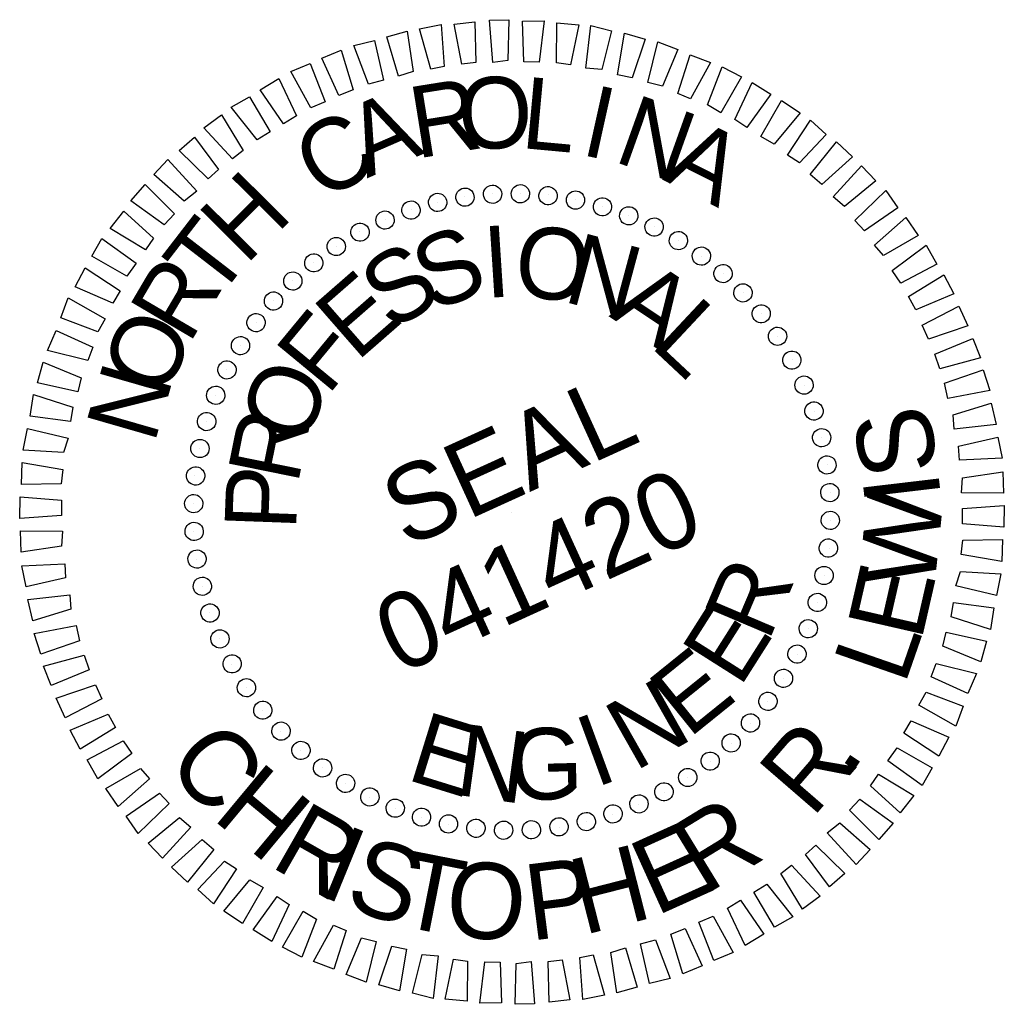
# Model space of a CAD drawing. Extents: x 2247910 to 2249896, y 662531 to 664300.
# Drawn here: x 2249756.6 to 2249834.1, y 664222.2 to 664299.8 of the extents above; entities that cross this region are included whole.
import ezdxf

# ---------------------------------------------------------------- set-up
doc = ezdxf.new("R2010")
doc.units = 0
doc.layers.add('Sheet PE Seal Cell', color=7, linetype='Continuous')

msp = doc.modelspace()

# ---------------------------------------------------------------- linework, layer by layer
at = {"layer": 'Sheet PE Seal Cell'}
for p, q in [((2249793.82, 664286.071), (2249793.82, 664286.071)), ((2249796.013, 664286.082), (2249796.013, 664286.082)), ((2249798.202, 664285.98), (2249798.202, 664285.98)), ((2249789.521, 664285.376), (2249789.521, 664285.376)), ((2249791.619, 664285.838), (2249791.619, 664285.838)), ((2249800.359, 664285.589), (2249800.359, 664285.589)), ((2249787.42, 664284.803), (2249787.42, 664284.803)), ((2249802.511, 664285.086), (2249802.511, 664285.086)), ((2249804.543, 664284.364), (2249804.543, 664284.364)), ((2249785.356, 664284.027), (2249785.356, 664284.027)), ((2249783.374, 664283.07), (2249783.374, 664283.07)), ((2249806.592, 664283.485), (2249806.592, 664283.485)), ((2249808.456, 664282.411), (2249808.456, 664282.411)), ((2249781.542, 664281.905), (2249781.542, 664281.905)), ((2249779.706, 664280.629), (2249779.706, 664280.629)), ((2249810.29, 664281.159), (2249810.29, 664281.159)), ((2249812.008, 664279.799), (2249812.008, 664279.799)), ((2249778.044, 664279.212), (2249778.044, 664279.212)), ((2249813.566, 664278.31), (2249813.566, 664278.31)), ((2249776.556, 664277.655), (2249776.556, 664277.655)), ((2249814.982, 664276.648), (2249814.982, 664276.648)), ((2249775.196, 664275.936), (2249775.196, 664275.936)), ((2249816.259, 664274.812), (2249816.259, 664274.812)), ((2249773.944, 664274.102), (2249773.944, 664274.102)), ((2249817.423, 664272.98), (2249817.423, 664272.98)), ((2249772.87, 664272.239), (2249772.87, 664272.239)), ((2249818.381, 664270.999), (2249818.381, 664270.999)), ((2249771.99, 664270.19), (2249771.99, 664270.19)), ((2249819.157, 664268.935), (2249819.157, 664268.935)), ((2249771.268, 664268.157), (2249771.268, 664268.157)), ((2249819.73, 664266.833), (2249819.73, 664266.833)), ((2249770.765, 664266.005), (2249770.765, 664266.005)), ((2249820.191, 664264.736), (2249820.191, 664264.736)), ((2249770.374, 664263.849), (2249770.374, 664263.849)), ((2249820.425, 664262.535), (2249820.425, 664262.535)), ((2249770.273, 664261.66), (2249770.273, 664261.66)), ((2249795.354, 664261), (2249795.354, 664261)), ((2249820.435, 664260.341), (2249820.435, 664260.341)), ((2249770.283, 664259.466), (2249770.283, 664259.466)), ((2249820.334, 664258.152), (2249820.334, 664258.152)), ((2249770.517, 664257.265), (2249770.517, 664257.265)), ((2249819.943, 664255.996), (2249819.943, 664255.996)), ((2249770.978, 664255.168), (2249770.978, 664255.168)), ((2249819.44, 664253.844), (2249819.44, 664253.844)), ((2249771.551, 664253.066), (2249771.551, 664253.066)), ((2249818.718, 664251.811), (2249818.718, 664251.811)), ((2249772.327, 664251.002), (2249772.327, 664251.002)), ((2249817.838, 664249.762), (2249817.838, 664249.762)), ((2249773.285, 664249.021), (2249773.285, 664249.021)), ((2249774.449, 664247.189), (2249774.449, 664247.189)), ((2249816.764, 664247.899), (2249816.764, 664247.899)), ((2249815.512, 664246.065), (2249815.512, 664246.065)), ((2249775.726, 664245.353), (2249775.726, 664245.353)), ((2249814.152, 664244.346), (2249814.152, 664244.346)), ((2249777.142, 664243.691), (2249777.142, 664243.691)), ((2249812.664, 664242.789), (2249812.664, 664242.789)), ((2249778.7, 664242.202), (2249778.7, 664242.202)), ((2249811.002, 664241.372), (2249811.002, 664241.372)), ((2249780.418, 664240.842), (2249780.418, 664240.842)), ((2249782.252, 664239.59), (2249782.252, 664239.59)), ((2249809.166, 664240.096), (2249809.166, 664240.096)), ((2249807.334, 664238.931), (2249807.334, 664238.931)), ((2249784.116, 664238.516), (2249784.116, 664238.516)), ((2249805.352, 664237.973), (2249805.352, 664237.973)), ((2249786.165, 664237.637), (2249786.165, 664237.637)), ((2249803.288, 664237.198), (2249803.288, 664237.198)), ((2249788.197, 664236.915), (2249788.197, 664236.915)), ((2249790.349, 664236.412), (2249790.349, 664236.412)), ((2249801.187, 664236.625), (2249801.187, 664236.625)), ((2249792.506, 664236.021), (2249792.506, 664236.021)), ((2249794.695, 664235.919), (2249794.695, 664235.919)), ((2249796.888, 664235.93), (2249796.888, 664235.93)), ((2249799.089, 664236.163), (2249799.089, 664236.163))]:
    msp.add_line(p, q, dxfattribs=at)
for points in [[(2249788.961, 664295.89), (2249788.068, 664299.055), (2249789.781, 664299.396), (2249790.02, 664296.098)], [(2249791.414, 664296.294), (2249790.811, 664299.426), (2249792.429, 664299.614), (2249792.515, 664296.411)], [(2249793.835, 664296.408), (2249793.575, 664299.751), (2249795.098, 664299.786), (2249795.027, 664296.567)], [(2249796.276, 664296.477), (2249796.191, 664299.679), (2249797.891, 664299.685), (2249797.506, 664296.432)], [(2249798.846, 664296.384), (2249798.893, 664299.537), (2249800.61, 664299.386), (2249799.96, 664296.232)], [(2249801.181, 664295.964), (2249801.57, 664299.329), (2249803.189, 664298.912), (2249802.43, 664295.874)], [(2249786.412, 664295.334), (2249785.495, 664298.432), (2249787.1, 664298.889), (2249787.567, 664295.695)], [(2249803.668, 664295.449), (2249804.211, 664298.719), (2249805.85, 664298.257), (2249804.823, 664295.206)], [(2249784.063, 664294.702), (2249782.897, 664297.743), (2249784.523, 664298.154), (2249785.238, 664295.018)], [(2249806.04, 664294.827), (2249806.827, 664298.043), (2249808.417, 664297.448), (2249807.215, 664294.538)], [(2249781.726, 664293.802), (2249780.378, 664296.76), (2249781.9, 664297.398), (2249782.838, 664294.254)], [(2249808.403, 664293.98), (2249809.385, 664297.01), (2249810.975, 664296.416), (2249809.417, 664293.564)], [(2249779.521, 664292.853), (2249777.946, 664295.706), (2249779.468, 664296.345), (2249780.634, 664293.305)], [(2249810.742, 664293.068), (2249811.902, 664296.069), (2249813.417, 664295.276), (2249811.794, 664292.448)], [(2249777.35, 664291.588), (2249775.522, 664294.272), (2249776.986, 664295.159), (2249778.379, 664292.223)], [(2249812.916, 664291.916), (2249814.274, 664294.843), (2249815.74, 664293.917), (2249813.856, 664291.3)], [(2249775.29, 664290.32), (2249773.235, 664292.9), (2249774.674, 664293.721), (2249776.32, 664290.954)], [(2249814.949, 664290.589), (2249816.572, 664293.417), (2249818.059, 664292.446), (2249816, 664289.97)], [(2249773.334, 664288.825), (2249771.072, 664291.256), (2249772.474, 664292.279), (2249774.186, 664289.487)], [(2249817.044, 664289.126), (2249818.866, 664291.88), (2249820.1, 664290.739), (2249817.984, 664288.511)], [(2249771.42, 664287.238), (2249769.129, 664289.491), (2249770.353, 664290.543), (2249772.23, 664287.992)], [(2249818.845, 664287.585), (2249820.908, 664290.173), (2249822.163, 664288.986), (2249819.757, 664286.791)], [(2249769.522, 664285.494), (2249767.137, 664287.594), (2249768.253, 664288.762), (2249770.535, 664286.285)], [(2249820.639, 664285.819), (2249822.875, 664288.267), (2249824.018, 664287.085), (2249821.529, 664285.071)], [(2249767.955, 664283.626), (2249765.338, 664285.511), (2249766.459, 664286.79), (2249768.77, 664284.492)], [(2249822.362, 664283.967), (2249824.797, 664286.341), (2249825.754, 664284.964), (2249823.116, 664283.157)], [(2249766.497, 664281.643), (2249763.694, 664283.333), (2249764.772, 664284.703), (2249767.112, 664282.583)], [(2249823.903, 664282.032), (2249826.376, 664284.203), (2249827.354, 664282.78), (2249824.612, 664281.201)], [(2249765.013, 664279.593), (2249762.272, 664281.146), (2249763.061, 664282.55), (2249765.765, 664280.595)], [(2249825.308, 664280.035), (2249827.975, 664282.019), (2249828.816, 664280.535), (2249825.987, 664279.026)], [(2249763.906, 664277.44), (2249760.954, 664278.733), (2249761.747, 664280.248), (2249764.501, 664278.426)], [(2249826.576, 664277.975), (2249829.368, 664279.687), (2249830.163, 664278.181), (2249827.165, 664276.925)], [(2249762.729, 664275.2), (2249759.815, 664276.29), (2249760.409, 664277.88), (2249763.303, 664276.231)], [(2249827.658, 664275.721), (2249830.553, 664277.205), (2249831.258, 664275.658), (2249828.156, 664274.629)], [(2249761.953, 664272.924), (2249758.783, 664273.732), (2249759.443, 664275.297), (2249762.349, 664273.984)], [(2249828.649, 664273.425), (2249831.648, 664274.682), (2249832.241, 664273.139), (2249829.056, 664272.292)], [(2249761.148, 664270.469), (2249757.974, 664271.166), (2249758.436, 664272.805), (2249761.412, 664271.578)], [(2249829.417, 664271.138), (2249832.453, 664272.192), (2249832.976, 664270.562), (2249829.687, 664269.942)], [(2249760.571, 664268.118), (2249757.409, 664268.546), (2249757.673, 664270.259), (2249760.769, 664269.252)], [(2249830.11, 664268.651), (2249833.097, 664269.573), (2249833.484, 664267.881), (2249830.182, 664267.53)], [(2249760.036, 664265.676), (2249756.866, 664265.88), (2249757.195, 664267.569), (2249760.39, 664266.827)], [(2249830.514, 664266.198), (2249833.605, 664266.892), (2249833.97, 664265.245), (2249830.586, 664265.077)], [(2249759.835, 664263.222), (2249756.723, 664263.178), (2249756.763, 664264.899), (2249759.987, 664264.336)], [(2249830.827, 664263.703), (2249834.021, 664264.169), (2249834.072, 664262.489), (2249830.762, 664262.519)], [(2249759.879, 664260.715), (2249756.581, 664260.476), (2249756.621, 664262.197), (2249759.878, 664261.923)], [(2249830.829, 664261.286), (2249834.127, 664261.525), (2249834.087, 664259.804), (2249830.83, 664260.078)], [(2249759.881, 664258.298), (2249756.687, 664257.832), (2249756.636, 664259.512), (2249759.946, 664259.482)], [(2249830.873, 664258.779), (2249833.985, 664258.823), (2249833.945, 664257.102), (2249830.721, 664257.665)], [(2249760.194, 664255.803), (2249757.103, 664255.109), (2249756.738, 664256.756), (2249760.123, 664256.924)], [(2249830.672, 664256.325), (2249833.842, 664256.121), (2249833.513, 664254.432), (2249830.318, 664255.174)], [(2249760.598, 664253.35), (2249757.611, 664252.428), (2249757.224, 664254.12), (2249760.526, 664254.471)], [(2249830.137, 664253.883), (2249833.299, 664253.455), (2249833.035, 664251.742), (2249829.939, 664252.749)], [(2249761.291, 664250.863), (2249758.255, 664249.809), (2249757.732, 664251.439), (2249761.021, 664252.059)], [(2249829.56, 664251.532), (2249832.734, 664250.835), (2249832.272, 664249.196), (2249829.296, 664250.423)], [(2249762.059, 664248.576), (2249759.06, 664247.319), (2249758.467, 664248.862), (2249761.652, 664249.709)], [(2249828.755, 664249.077), (2249831.926, 664248.269), (2249831.265, 664246.704), (2249828.359, 664248.017)], [(2249763.05, 664246.28), (2249760.155, 664244.796), (2249759.45, 664246.343), (2249762.552, 664247.372)], [(2249827.979, 664246.801), (2249830.893, 664245.711), (2249830.299, 664244.121), (2249827.405, 664245.77)], [(2249764.132, 664244.026), (2249761.34, 664242.314), (2249760.545, 664243.82), (2249763.543, 664245.076)], [(2249826.802, 664244.561), (2249829.754, 664243.268), (2249828.961, 664241.753), (2249826.207, 664243.575)], [(2249765.4, 664241.966), (2249762.733, 664239.982), (2249761.892, 664241.466), (2249764.721, 664242.975)], [(2249825.695, 664242.408), (2249828.436, 664240.855), (2249827.647, 664239.451), (2249824.943, 664241.406)], [(2249766.805, 664239.969), (2249764.332, 664237.798), (2249763.354, 664239.221), (2249766.096, 664240.8)], [(2249824.211, 664240.358), (2249827.014, 664238.668), (2249825.936, 664237.298), (2249823.596, 664239.418)], [(2249768.346, 664238.034), (2249765.911, 664235.66), (2249764.954, 664237.037), (2249767.592, 664238.844)], [(2249822.753, 664238.375), (2249825.37, 664236.49), (2249824.249, 664235.211), (2249821.938, 664237.509)], [(2249770.069, 664236.182), (2249767.833, 664233.734), (2249766.69, 664234.916), (2249769.179, 664236.93)], [(2249821.186, 664236.507), (2249823.571, 664234.407), (2249822.455, 664233.239), (2249820.173, 664235.716)], [(2249771.863, 664234.416), (2249769.8, 664231.828), (2249768.545, 664233.015), (2249770.952, 664235.21)], [(2249819.288, 664234.763), (2249821.579, 664232.51), (2249820.355, 664231.458), (2249818.478, 664234.009)], [(2249773.664, 664232.875), (2249771.842, 664230.121), (2249770.608, 664231.262), (2249772.724, 664233.49)], [(2249817.374, 664233.176), (2249819.636, 664230.745), (2249818.234, 664229.722), (2249816.522, 664232.514)], [(2249775.759, 664231.412), (2249774.136, 664228.584), (2249772.649, 664229.555), (2249774.708, 664232.031)], [(2249815.418, 664231.681), (2249817.473, 664229.101), (2249816.034, 664228.28), (2249814.388, 664231.047)], [(2249777.792, 664230.085), (2249776.434, 664227.158), (2249774.968, 664228.084), (2249776.852, 664230.701)], [(2249813.358, 664230.413), (2249815.186, 664227.729), (2249813.722, 664226.842), (2249812.329, 664229.778)], [(2249779.966, 664228.933), (2249778.806, 664225.932), (2249777.291, 664226.725), (2249778.914, 664229.553)], [(2249811.187, 664229.148), (2249812.762, 664226.295), (2249811.24, 664225.656), (2249810.074, 664228.696)], [(2249782.305, 664228.021), (2249781.323, 664224.991), (2249779.733, 664225.585), (2249781.291, 664228.437)], [(2249808.982, 664228.199), (2249810.33, 664225.241), (2249808.808, 664224.603), (2249807.87, 664227.747)], [(2249784.668, 664227.174), (2249783.881, 664223.958), (2249782.291, 664224.553), (2249783.493, 664227.463)], [(2249806.645, 664227.299), (2249807.811, 664224.258), (2249806.185, 664223.847), (2249805.47, 664226.983)], [(2249787.04, 664226.552), (2249786.497, 664223.282), (2249784.858, 664223.744), (2249785.885, 664226.795)], [(2249804.296, 664226.667), (2249805.213, 664223.569), (2249803.608, 664223.112), (2249803.141, 664226.306)], [(2249789.527, 664226.037), (2249789.138, 664222.672), (2249787.519, 664223.089), (2249788.278, 664226.127)], [(2249791.862, 664225.617), (2249791.815, 664222.464), (2249790.098, 664222.615), (2249790.748, 664225.769)], [(2249794.432, 664225.524), (2249794.517, 664222.322), (2249792.817, 664222.316), (2249793.203, 664225.569)], [(2249796.873, 664225.593), (2249797.133, 664222.25), (2249795.61, 664222.215), (2249795.681, 664225.434)], [(2249799.294, 664225.707), (2249799.897, 664222.575), (2249798.279, 664222.387), (2249798.193, 664225.59)], [(2249801.747, 664226.111), (2249802.64, 664222.946), (2249800.927, 664222.605), (2249800.688, 664225.903)]]:
    msp.add_lwpolyline(points, close=True, dxfattribs=at)
for centre, major_axis in [((2249793.824, 664286.034), (-0.044, 0.719)), ((2249796.011, 664286.072), (0.019, 0.72)), ((2249789.5, 664285.388), (-0.168, 0.7)), ((2249791.648, 664285.805), (-0.106, 0.712)), ((2249798.194, 664285.919), (0.082, 0.715)), ((2249800.355, 664285.577), (0.144, 0.706)), ((2249787.397, 664284.785), (-0.228, 0.683)), ((2249802.478, 664285.047), (0.205, 0.69)), ((2249804.547, 664284.335), (0.264, 0.67)), ((2249785.354, 664284.001), (-0.287, 0.66)), ((2249783.388, 664283.042), (-0.344, 0.633)), ((2249806.545, 664283.445), (0.321, 0.644)), ((2249808.459, 664282.384), (0.376, 0.614)), ((2249781.512, 664281.915), (-0.397, 0.6)), ((2249779.742, 664280.629), (-0.448, 0.563)), ((2249810.273, 664281.161), (0.428, 0.579)), ((2249811.973, 664279.784), (0.477, 0.539)), ((2249778.091, 664279.194), (-0.496, 0.522)), ((2249813.547, 664278.264), (0.522, 0.496)), ((2249776.571, 664277.62), (-0.539, 0.477)), ((2249814.982, 664276.612), (0.563, 0.448)), ((2249775.194, 664275.919), (-0.579, 0.428)), ((2249816.268, 664274.842), (0.6, 0.397)), ((2249773.97, 664274.106), (-0.614, 0.376)), ((2249817.395, 664272.967), (0.633, 0.344)), ((2249772.909, 664272.192), (-0.644, 0.321)), ((2249818.354, 664271), (0.66, 0.287)), ((2249772.019, 664270.193), (-0.67, 0.264)), ((2249819.138, 664268.958), (0.683, 0.228)), ((2249771.307, 664268.124), (-0.69, 0.205)), ((2249819.741, 664266.854), (0.7, 0.168)), ((2249770.778, 664266.002), (-0.706, 0.144)), ((2249820.159, 664264.707), (0.712, 0.106)), ((2249770.435, 664263.841), (-0.715, 0.082)), ((2249820.387, 664262.531), (0.719, 0.044)), ((2249770.283, 664261.658), (-0.72, 0.019)), ((2249820.425, 664260.343), (0.72, -0.019)), ((2249770.321, 664259.47), (-0.719, -0.044)), ((2249820.273, 664258.16), (0.715, -0.082)), ((2249770.549, 664257.294), (-0.712, -0.106)), ((2249819.93, 664255.999), (0.706, -0.144)), ((2249770.967, 664255.147), (-0.7, -0.168)), ((2249819.401, 664253.877), (0.69, -0.205)), ((2249771.57, 664253.043), (-0.683, -0.228)), ((2249818.689, 664251.808), (0.67, -0.264)), ((2249772.354, 664251.001), (-0.66, -0.287)), ((2249817.799, 664249.809), (0.644, -0.321)), ((2249773.313, 664249.034), (-0.633, -0.344)), ((2249816.738, 664247.895), (0.614, -0.376)), ((2249774.44, 664247.159), (-0.6, -0.397)), ((2249815.514, 664246.082), (0.579, -0.428)), ((2249775.726, 664245.389), (-0.563, -0.448)), ((2249814.137, 664244.381), (0.539, -0.477)), ((2249777.161, 664243.737), (-0.522, -0.496)), ((2249812.617, 664242.807), (0.496, -0.522)), ((2249778.735, 664242.217), (-0.477, -0.539)), ((2249810.966, 664241.372), (0.448, -0.563)), ((2249780.435, 664240.84), (-0.428, -0.579)), ((2249782.249, 664239.617), (-0.376, -0.614)), ((2249809.196, 664240.086), (0.397, -0.6)), ((2249784.163, 664238.556), (-0.321, -0.644)), ((2249807.32, 664238.959), (0.344, -0.633)), ((2249805.354, 664238), (0.287, -0.66)), ((2249786.161, 664237.666), (-0.264, -0.67)), ((2249803.311, 664237.216), (0.228, -0.683)), ((2249788.23, 664236.954), (-0.205, -0.69)), ((2249790.353, 664236.424), (-0.144, -0.706)), ((2249801.208, 664236.613), (0.168, -0.7)), ((2249792.514, 664236.082), (-0.082, -0.715)), ((2249794.697, 664235.929), (-0.019, -0.72)), ((2249796.884, 664235.967), (0.044, -0.719)), ((2249799.06, 664236.196), (0.106, -0.712))]:
    msp.add_ellipse(centre, major_axis=major_axis, ratio=0.999708, dxfattribs=at)

# ---------------------------------------------------------------- texts
for s, height, rotation, p in [('O', 5.638, 1.91911, (2249791.193, 664289.545)), ('L', 5.638, 354.71882, (2249795.964, 664289.686)), ('R', 5.638, 9.11904, (2249787.834, 664288.838)), ('I', 5.638, 347.51808, (2249800.645, 664289.181)), ('N', 5.639, 340.31685, (2249803.244, 664288.662)), ('A', 5.638, 23.51826, (2249783.929, 664287.279)), ('C', 5.638, 30.71781, (2249780.459, 664285.368)), ('A', 5.639, 333.1151, (2249807.152, 664287.201)), ('H', 5.638, 45.11742, (2249774.372, 664280.396)), ('T', 5.638, 52.31772, (2249772.099, 664277.547)), ('S', 5.638, 22.39834, (2249789.074, 664276.711)), ('I', 5.638, 3.68755, (2249793.277, 664277.857)), ('O', 5.638, 354.33143, (2249795.388, 664278.049)), ('N', 5.639, 344.97455, (2249799.265, 664277.618)), ('S', 5.638, 31.75355, (2249785.819, 664275.173)), ('R', 5.639, 59.51845, (2249769.918, 664274.135)), ('E', 5.638, 41.10901, (2249783.115, 664272.786)), ('A', 5.639, 326.25821, (2249802.937, 664276.434)), ('L', 5.639, 316.89879, (2249806.142, 664274.103)), ('F', 5.638, 50.46498, (2249780.825, 664270.095)), ('O', 5.638, 66.71968, (2249768.064, 664269.884)), ('N', 5.639, 73.92144, (2249767.173, 664266.291)), ('O', 5.639, 69.17918, (2249779.045, 664266.042)), ('SEAL', 5.9982, 24.49794, (2249786.995, 664258.124)), ('S', 5.998, 100.55241, (2249829.001, 664264.402)), ('R', 5.639, 78.53759, (2249778.469, 664263.087)), ('P', 5.639, 87.89683, (2249778.34, 664259.511)), ('041420', 5.9982, 24.49794, (2249786.445, 664248.14)), ('I', 5.998, 96.75046, (2249829.152, 664262.163)), ('W', 5.998, 84.21639, (2249828.599, 664254.801)), ('R', 5.639, 66.97935, (2249815.545, 664250.695)), ('E', 5.998, 77.10705, (2249827.576, 664250.734)), ('E', 5.638, 57.62203, (2249813.289, 664247.085)), ('L', 5.998, 70.83229, (2249826.261, 664247.274)), ('E', 5.638, 38.9097, (2249809.275, 664243.112)), ('N', 5.638, 29.55433, (2249805.019, 664240.514)), ('E', 5.638, 342.77483, (2249786.92, 664239.959)), ('I', 5.638, 20.19914, (2249801.908, 664239.261)), ('N', 5.639, 352.1319, (2249790.769, 664238.746)), ('G', 5.638, 1.48818, (2249795.16, 664238.274)), ('R', 5.998, 49.11789, (2249818.989, 664236.813)), ('C', 5.998, 310.69992, (2249767.967, 664241.161)), ('.', 5.998, 56.59815, (2249821.937, 664240.096)), ('H', 5.998, 320.28207, (2249771.651, 664236.879)), ('R', 5.998, 330.26605, (2249776.192, 664233.135)), ('R', 5.998, 31.43728, (2249810.527, 664230.777)), ('E', 5.998, 24.32794, (2249806.669, 664229.132)), ('I', 5.998, 337.74631, (2249779.983, 664230.877)), ('S', 5.998, 341.54826, (2249782.014, 664229.924)), ('H', 5.998, 14.34395, (2249800.973, 664227.652)), ('T', 5.998, 348.87397, (2249786.086, 664228.477)), ('O', 5.998, 355.67421, (2249790.002, 664227.609)), ('P', 5.998, 7.23461, (2249796.802, 664227.213))]:
    msp.add_text(s, height=height, rotation=rotation, dxfattribs=at).set_placement(p)

doc.saveas('drawing.dxf')
